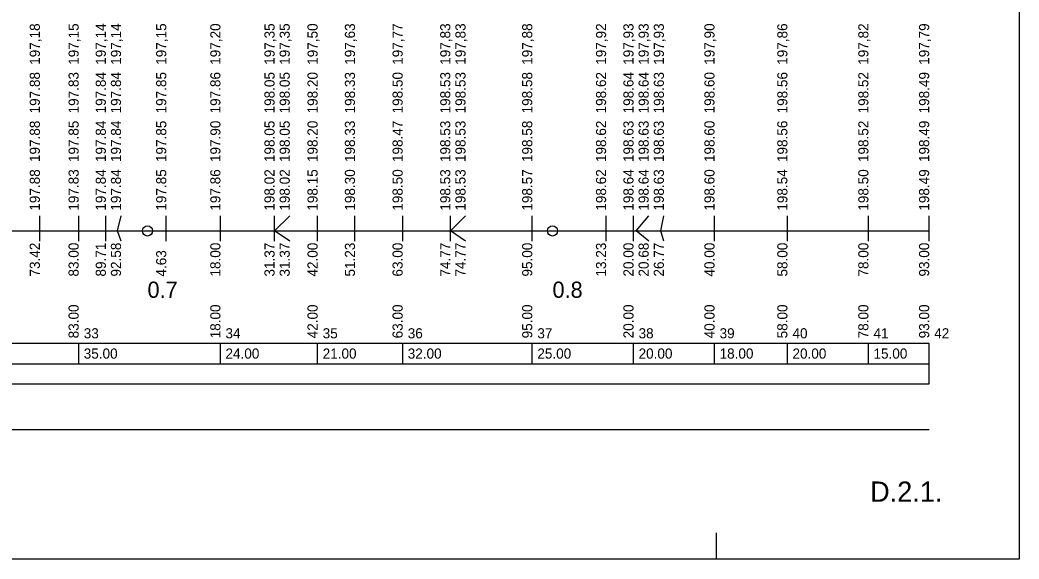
# Model space of a CAD drawing. Extents: x -51 to 53, y -74 to 15.
# Drawn here: x 28.41 to 53.08, y -73.95 to -60.64 of the extents above; entities that cross this region are included whole.
import ezdxf

# ---------------------------------------------------------------- set-up
doc = ezdxf.new("R2010")
doc.units = 0
for name, color, linetype in [('Implicitní', 7, 'Continuous'), ('KOTY_L', 7, 'Continuous'), ('KOTY_N', 7, 'Continuous'), ('KOTY_S', 7, 'Continuous'), ('KOTY_T', 7, 'Continuous'), ('KOTY_VP', 7, 'Continuous'), ('Nová vrstva (0)', 7, 'Continuous'), ('ROVINA_100', 7, 'Continuous'), ('ROVINA_L', 7, 'Continuous'), ('ROVINA_O', 7, 'Continuous'), ('SMP_L', 7, 'Continuous'), ('TABULKY_L', 7, 'Continuous'), ('TABULKY_T', 7, 'Continuous')]:
    doc.layers.add(name, color=color, linetype=linetype)

msp = doc.modelspace()

# ---------------------------------------------------------------- linework, layer by layer
at = {"layer": 'Implicitní'}
msp.add_line((45.608, -73.946), (45.608, -73.297), dxfattribs=at)
msp.add_lwpolyline([(-51.392, -44.246), (53.079, -44.246), (53.079, -73.946), (-51.392, -73.946)], close=True, dxfattribs=at)
at = {"layer": 'KOTY_L'}
for p, q in [((28.902, -64.151), (28.902, -64.151)), ((29.86, -64.151), (29.86, -64.151)), ((30.531, -64.151), (30.531, -64.151)), ((30.906, -64.151), (30.906, -64.151)), ((32.023, -64.151), (32.023, -64.151)), ((33.36, -64.151), (33.36, -64.151)), ((34.697, -64.151), (34.697, -64.151)), ((35.072, -64.151), (35.072, -64.151)), ((35.76, -64.151), (35.76, -64.151)), ((36.683, -64.151), (36.683, -64.151)), ((37.86, -64.151), (37.86, -64.151)), ((39.037, -64.151), (39.037, -64.151)), ((39.412, -64.151), (39.412, -64.151)), ((41.06, -64.151), (41.06, -64.151)), ((42.883, -64.151), (42.883, -64.151)), ((43.56, -64.151), (43.56, -64.151)), ((43.935, -64.151), (43.935, -64.151)), ((44.31, -64.151), (44.31, -64.151)), ((45.56, -64.151), (45.56, -64.151)), ((47.36, -64.151), (47.36, -64.151)), ((49.36, -64.151), (49.36, -64.151)), ((50.86, -64.151), (50.86, -64.151)), ((28.902, -65.851), (28.902, -65.476)), ((29.86, -65.851), (29.86, -65.476)), ((30.531, -65.851), (30.531, -65.476)), ((30.818, -65.851), (30.906, -65.476)), ((32.023, -65.851), (32.023, -65.476)), ((33.36, -65.851), (33.36, -65.476)), ((34.697, -65.851), (34.697, -65.476)), ((34.697, -65.851), (35.072, -65.476)), ((35.76, -65.851), (35.76, -65.476)), ((36.683, -65.851), (36.683, -65.476)), ((37.86, -65.851), (37.86, -65.476)), ((39.037, -65.851), (39.037, -65.476)), ((39.037, -65.851), (39.412, -65.476)), ((41.06, -65.851), (41.06, -65.476)), ((42.883, -65.851), (42.883, -65.476)), ((43.56, -65.851), (43.56, -65.476)), ((43.628, -65.851), (43.935, -65.476)), ((44.237, -65.851), (44.31, -65.476)), ((45.56, -65.851), (45.56, -65.476)), ((47.36, -65.851), (47.36, -65.476)), ((49.36, -65.851), (49.36, -65.476)), ((50.86, -65.851), (50.86, -65.476))]:
    msp.add_line(p, q, dxfattribs=at)
at = {"layer": 'KOTY_S'}
for p, q in [((28.902, -66.101), (28.902, -65.851)), ((29.86, -66.101), (29.86, -65.851)), ((30.531, -66.101), (30.531, -65.851)), ((30.906, -66.101), (30.818, -65.851)), ((32.023, -66.101), (32.023, -65.851)), ((33.36, -66.101), (33.36, -65.851)), ((34.697, -66.101), (34.697, -65.851)), ((35.072, -66.101), (34.697, -65.851)), ((35.76, -66.101), (35.76, -65.851)), ((36.683, -66.101), (36.683, -65.851)), ((37.86, -66.101), (37.86, -65.851)), ((39.037, -66.101), (39.037, -65.851)), ((39.412, -66.101), (39.037, -65.851)), ((41.06, -66.101), (41.06, -65.851)), ((42.883, -66.101), (42.883, -65.851)), ((43.56, -66.101), (43.56, -65.851)), ((43.935, -66.101), (43.628, -65.851)), ((44.31, -66.101), (44.237, -65.851)), ((45.56, -66.101), (45.56, -65.851)), ((47.36, -66.101), (47.36, -65.851)), ((49.36, -66.101), (49.36, -65.851)), ((50.86, -66.101), (50.86, -65.851))]:
    msp.add_line(p, q, dxfattribs=at)
at = {"layer": 'ROVINA_L'}
msp.add_line((-38.44, -65.851), (50.86, -65.851), dxfattribs=at)
at = {"layer": 'ROVINA_O'}
for centre in [(31.56, -65.851), (41.56, -65.851)]:
    msp.add_circle(centre, 0.125, dxfattribs=at)
at = {"layer": 'SMP_L'}
msp.add_line((24.26, -70.751), (50.86, -70.751), dxfattribs=at)
at = {"layer": 'TABULKY_L'}
for p, q in [((50.86, -68.626), (-38.44, -68.626)), ((29.86, -69.126), (29.86, -68.626)), ((33.36, -69.126), (33.36, -68.626)), ((35.76, -69.126), (35.76, -68.626)), ((37.86, -69.126), (37.86, -68.626)), ((41.06, -69.126), (41.06, -68.626)), ((43.56, -69.126), (43.56, -68.626)), ((45.56, -69.126), (45.56, -68.626)), ((47.36, -69.126), (47.36, -68.626)), ((49.36, -69.126), (49.36, -68.626)), ((50.86, -69.126), (50.86, -68.626)), ((50.86, -69.626), (50.86, -68.626)), ((-38.44, -69.126), (50.86, -69.126)), ((50.86, -69.626), (50.86, -69.126)), ((-38.44, -69.626), (50.86, -69.626))]:
    msp.add_line(p, q, dxfattribs=at)

# ---------------------------------------------------------------- texts
at = {"layer": 'Implicitní'}
msp.add_text('D.2.1.', height=0.5, dxfattribs=at).set_placement((49.402, -72.533))
at = {"layer": 'KOTY_N'}
for s, p in [('197.88', (28.902, -64.151)), ('197.85', (29.86, -64.151)), ('197.84', (30.531, -64.151)), ('197.84', (30.906, -64.151)), ('197.85', (32.023, -64.151)), ('197.90', (33.36, -64.151)), ('198.05', (34.697, -64.151)), ('198.05', (35.072, -64.151)), ('198.20', (35.76, -64.151)), ('198.33', (36.683, -64.151)), ('198.47', (37.86, -64.151)), ('198.53', (39.037, -64.151)), ('198.53', (39.412, -64.151)), ('198.58', (41.06, -64.151)), ('198.62', (42.883, -64.151)), ('198.63', (43.56, -64.151)), ('198.63', (43.935, -64.151)), ('198.63', (44.31, -64.151)), ('198.60', (45.56, -64.151)), ('198.56', (47.36, -64.151)), ('198.52', (49.36, -64.151)), ('198.49', (50.86, -64.151))]:
    msp.add_text(s, height=0.25, rotation=90, dxfattribs=at).set_placement(p)
at = {"layer": 'KOTY_S'}
for s, p in [('73.42', (28.902, -66.976)), ('83.00', (29.86, -66.976)), ('89.71', (30.531, -66.976)), ('92.58', (30.906, -66.976)), ('4.63', (32.023, -66.976)), ('18.00', (33.36, -66.976)), ('31.37', (34.697, -66.976)), ('31.37', (35.072, -66.976)), ('42.00', (35.76, -66.976)), ('51.23', (36.683, -66.976)), ('63.00', (37.86, -66.976)), ('74.77', (39.037, -66.976)), ('74.77', (39.412, -66.976)), ('95.00', (41.06, -66.976)), ('13.23', (42.883, -66.976)), ('20.00', (43.56, -66.976)), ('20.68', (43.935, -66.976)), ('26.77', (44.31, -66.976)), ('40.00', (45.56, -66.976)), ('58.00', (47.36, -66.976)), ('78.00', (49.36, -66.976)), ('93.00', (50.86, -66.976))]:
    msp.add_text(s, height=0.25, rotation=90, dxfattribs=at).set_placement(p)
at = {"layer": 'KOTY_T'}
for s, p in [('197.88', (28.902, -65.351)), ('197.83', (29.86, -65.351)), ('197.84', (30.531, -65.351)), ('197.84', (30.906, -65.351)), ('197.85', (32.023, -65.351)), ('197.86', (33.36, -65.351)), ('198.02', (34.697, -65.351)), ('198.02', (35.072, -65.351)), ('198.15', (35.76, -65.351)), ('198.30', (36.683, -65.351)), ('198.50', (37.86, -65.351)), ('198.53', (39.037, -65.351)), ('198.53', (39.412, -65.351)), ('198.57', (41.06, -65.351)), ('198.62', (42.883, -65.351)), ('198.64', (43.56, -65.351)), ('198.64', (43.935, -65.351)), ('198.63', (44.31, -65.351)), ('198.60', (45.56, -65.351)), ('198.54', (47.36, -65.351)), ('198.50', (49.36, -65.351)), ('198.49', (50.86, -65.351))]:
    msp.add_text(s, height=0.25, rotation=90, dxfattribs=at).set_placement(p)
at = {"layer": 'KOTY_VP'}
for s, p in [('197.88', (28.902, -62.951)), ('197.83', (29.86, -62.951)), ('197.84', (30.531, -62.951)), ('197.84', (30.906, -62.951)), ('197.85', (32.023, -62.951)), ('197.86', (33.36, -62.951)), ('198.05', (34.697, -62.951)), ('198.05', (35.072, -62.951)), ('198.20', (35.76, -62.951)), ('198.33', (36.683, -62.951)), ('198.50', (37.86, -62.951)), ('198.53', (39.037, -62.951)), ('198.53', (39.412, -62.951)), ('198.58', (41.06, -62.951)), ('198.62', (42.883, -62.951)), ('198.64', (43.56, -62.951)), ('198.64', (43.935, -62.951)), ('198.63', (44.31, -62.951)), ('198.60', (45.56, -62.951)), ('198.56', (47.36, -62.951)), ('198.52', (49.36, -62.951)), ('198.49', (50.86, -62.951))]:
    msp.add_text(s, height=0.25, rotation=90, dxfattribs=at).set_placement(p)
at = {"layer": 'Nová vrstva (0)'}
for s, p in [('197,18', (28.902, -61.751)), ('197,15', (29.86, -61.751)), ('197,14', (30.531, -61.751)), ('197,14', (30.906, -61.751)), ('197,15', (32.023, -61.751)), ('197,20', (33.36, -61.751)), ('197,35', (34.697, -61.751)), ('197,35', (35.072, -61.751)), ('197,50', (35.76, -61.751)), ('197,63', (36.683, -61.751)), ('197,77', (37.86, -61.751)), ('197,83', (39.037, -61.751)), ('197,83', (39.412, -61.751)), ('197,88', (41.06, -61.751)), ('197,92', (42.883, -61.751)), ('197,93', (43.56, -61.751)), ('197,93', (43.935, -61.751)), ('197,93', (44.31, -61.751)), ('197,90', (45.56, -61.751)), ('197,86', (47.36, -61.751)), ('197,82', (49.36, -61.751)), ('197,79', (50.86, -61.751))]:
    msp.add_text(s, height=0.25, rotation=90, dxfattribs=at).set_placement(p)
at = {"layer": 'ROVINA_100'}
for s, p in [('0.7', (31.56, -67.501)), ('0.8', (41.56, -67.501))]:
    msp.add_text(s, height=0.4, dxfattribs=at).set_placement(p)
at = {"layer": 'TABULKY_T'}
for s, p in [('83.00', (29.86, -68.501)), ('18.00', (33.36, -68.501)), ('42.00', (35.76, -68.501)), ('63.00', (37.86, -68.501)), ('95.00', (41.06, -68.501)), ('20.00', (43.56, -68.501)), ('40.00', (45.56, -68.501)), ('58.00', (47.36, -68.501)), ('78.00', (49.36, -68.501)), ('93.00', (50.86, -68.501))]:
    msp.add_text(s, height=0.25, rotation=90, dxfattribs=at).set_placement(p)
for s, p in [('33', (29.985, -68.501)), ('34', (33.485, -68.501)), ('35', (35.885, -68.501)), ('36', (37.985, -68.501)), ('37', (41.185, -68.501)), ('38', (43.685, -68.501)), ('39', (45.685, -68.501)), ('40', (47.485, -68.501)), ('41', (49.485, -68.501)), ('42', (50.985, -68.501)), ('35.00', (29.985, -69.001)), ('24.00', (33.485, -69.001)), ('21.00', (35.885, -69.001)), ('32.00', (37.985, -69.001)), ('25.00', (41.185, -69.001)), ('20.00', (43.685, -69.001)), ('18.00', (45.685, -69.001)), ('20.00', (47.485, -69.001)), ('15.00', (49.485, -69.001))]:
    msp.add_text(s, height=0.25, dxfattribs=at).set_placement(p)

doc.saveas('drawing.dxf')
